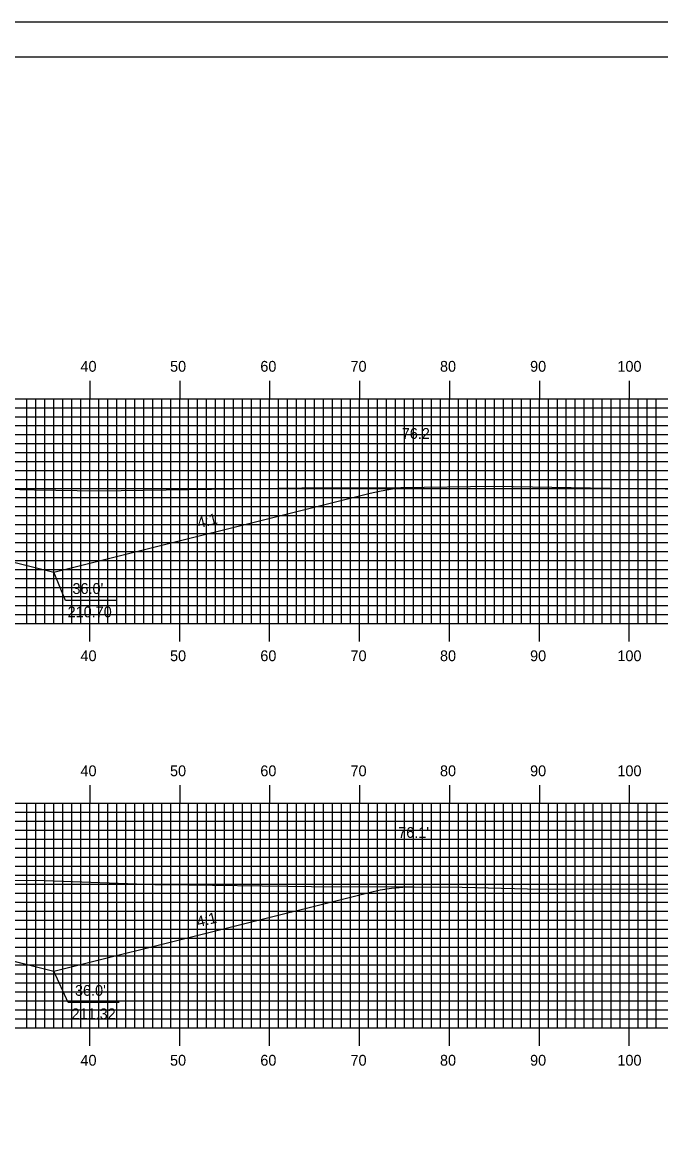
# Model space of a CAD drawing. Extents: x 1820818 to 1821161, y 442591 to 442811.
# Drawn here: x 1821016.2 to 1821087.2, y 442686.7 to 442810.5 of the extents above; entities that cross this region are included whole.
import ezdxf

# ---------------------------------------------------------------- set-up
doc = ezdxf.new("R2010")
doc.units = 0
for name, color, linetype in [('ANNOTATION', 7, 'Continuous'), ('BORDER', 7, 'Continuous'), ('D_Roadway_Centerline', 7, 'Continuous'), ('D_Roadway_SlopeLines', 7, 'Continuous'), ('D_Text_Standard', 7, 'Continuous'), ('H_V ANNOTATION', 7, 'Continuous'), ('MAJOR', 7, 'Continuous'), ('MINOR', 7, 'Continuous'), ('PLOT BOUNDARY', 7, 'Continuous'), ('S_Roadway_Centerline', 7, 'Continuous')]:
    doc.layers.add(name, color=color, linetype=linetype)

msp = doc.modelspace()

# ---------------------------------------------------------------- linework, layer by layer
at = {"layer": 'ANNOTATION'}
for points in [[(1821026.71, 442746.22), (1821021.02, 442746.22), (1821019.72, 442749.36)], [(1821027, 442701.51), (1821021.31, 442701.51), (1821019.72, 442704.99)]]:
    msp.add_lwpolyline(points, dxfattribs=at)
at = {"layer": 'BORDER'}
msp.add_lwpolyline([(1820834.12, 442596.67), (1821154.12, 442596.67), (1821154.12, 442806.67), (1820834.12, 442806.67)], close=True, dxfattribs=at)
at = {"layer": 'D_Roadway_Centerline'}
for points in [[(1820912.99, 442757.89), (1820914.24, 442757.86), (1820915.49, 442757.75), (1820916.74, 442757.56), (1820917.99, 442757.29), (1820949.54, 442749.4), (1820953.54, 442750.4), (1820963.72, 442752.94), (1820971.72, 442753.26), (1820983.72, 442753.5), (1820995.72, 442753.26), (1821005.72, 442752.86), (1821015.72, 442750.36), (1821019.72, 442749.36), (1821054.89, 442758.15), (1821056.14, 442758.43), (1821057.39, 442758.63), (1821058.64, 442758.75), (1821059.89, 442758.8)], [(1820905.5, 442715.37), (1820906.75, 442715.35), (1820908, 442715.24), (1820909.25, 442715.05), (1820910.5, 442714.78), (1820949.54, 442705.02), (1820953.54, 442706.02), (1820963.72, 442708.57), (1820971.72, 442708.89), (1820983.72, 442709.13), (1820995.72, 442708.89), (1821005.72, 442708.49), (1821015.72, 442705.99), (1821019.72, 442704.99), (1821054.78, 442713.75), (1821056.03, 442714.02), (1821057.28, 442714.22), (1821058.53, 442714.33), (1821059.78, 442714.37)]]:
    msp.add_lwpolyline(points, dxfattribs=at)
at = {"layer": 'D_Roadway_SlopeLines'}
for points in [[(1821019.72, 442749.36), (1821054.89, 442758.15), (1821056.14, 442758.43), (1821057.39, 442758.63), (1821058.64, 442758.75), (1821059.89, 442758.8)], [(1821005.72, 442752.86), (1821019.72, 442749.36)], [(1821019.72, 442704.99), (1821054.78, 442713.75), (1821056.03, 442714.02), (1821057.28, 442714.22), (1821058.53, 442714.33), (1821059.78, 442714.37)], [(1821005.72, 442708.49), (1821019.72, 442704.99)]]:
    msp.add_lwpolyline(points, dxfattribs=at)
at = {"layer": 'MAJOR'}
for p, q in [((1821023.72, 442770.67), (1821023.72, 442768.67)), ((1821033.72, 442770.67), (1821033.72, 442768.67)), ((1821043.72, 442770.67), (1821043.72, 442768.67)), ((1821053.72, 442770.67), (1821053.72, 442768.67)), ((1821063.72, 442770.67), (1821063.72, 442768.67)), ((1821073.72, 442770.67), (1821073.72, 442768.67)), ((1821083.72, 442770.67), (1821083.72, 442768.67)), ((1820843.72, 442768.67), (1821123.72, 442768.67)), ((1820843.72, 442768.67), (1821123.72, 442768.67)), ((1821023.72, 442743.67), (1821023.72, 442768.67)), ((1821033.72, 442743.67), (1821033.72, 442768.67)), ((1821043.72, 442743.67), (1821043.72, 442768.67)), ((1821053.72, 442743.67), (1821053.72, 442768.67)), ((1821063.72, 442743.67), (1821063.72, 442768.67)), ((1821073.72, 442743.67), (1821073.72, 442768.67)), ((1821083.72, 442743.67), (1821083.72, 442768.67)), ((1820843.72, 442763.67), (1821123.72, 442763.67)), ((1820843.72, 442758.67), (1821123.72, 442758.67)), ((1820843.72, 442753.67), (1821123.72, 442753.67)), ((1820843.72, 442748.67), (1821123.72, 442748.67)), ((1820843.72, 442743.67), (1821123.72, 442743.67)), ((1820843.72, 442743.67), (1821123.72, 442743.67)), ((1821023.72, 442741.66), (1821023.72, 442743.67)), ((1821033.72, 442741.66), (1821033.72, 442743.67)), ((1821043.72, 442741.66), (1821043.72, 442743.67)), ((1821053.72, 442741.66), (1821053.72, 442743.67)), ((1821063.72, 442741.66), (1821063.72, 442743.67)), ((1821073.72, 442741.66), (1821073.72, 442743.67)), ((1821083.72, 442741.66), (1821083.72, 442743.67)), ((1821023.72, 442725.67), (1821023.72, 442723.67)), ((1821033.72, 442725.67), (1821033.72, 442723.67)), ((1821043.72, 442725.67), (1821043.72, 442723.67)), ((1821053.72, 442725.67), (1821053.72, 442723.67)), ((1821063.72, 442725.67), (1821063.72, 442723.67)), ((1821073.72, 442725.67), (1821073.72, 442723.67)), ((1821083.72, 442725.67), (1821083.72, 442723.67)), ((1820843.72, 442723.67), (1821123.72, 442723.67)), ((1820843.72, 442723.67), (1821123.72, 442723.67)), ((1821023.72, 442698.67), (1821023.72, 442723.67)), ((1821033.72, 442698.67), (1821033.72, 442723.67)), ((1821043.72, 442698.67), (1821043.72, 442723.67)), ((1821053.72, 442698.67), (1821053.72, 442723.67)), ((1821063.72, 442698.67), (1821063.72, 442723.67)), ((1821073.72, 442698.67), (1821073.72, 442723.67)), ((1821083.72, 442698.67), (1821083.72, 442723.67)), ((1820843.72, 442718.67), (1821123.72, 442718.67)), ((1820843.72, 442713.67), (1821123.72, 442713.67)), ((1820843.72, 442708.67), (1821123.72, 442708.67)), ((1820843.72, 442703.67), (1821123.72, 442703.67)), ((1820843.72, 442698.67), (1821123.72, 442698.67)), ((1820843.72, 442698.67), (1821123.72, 442698.67)), ((1821023.72, 442696.66), (1821023.72, 442698.67)), ((1821033.72, 442696.66), (1821033.72, 442698.67)), ((1821043.72, 442696.66), (1821043.72, 442698.67)), ((1821053.72, 442696.66), (1821053.72, 442698.67)), ((1821063.72, 442696.66), (1821063.72, 442698.67)), ((1821073.72, 442696.66), (1821073.72, 442698.67)), ((1821083.72, 442696.66), (1821083.72, 442698.67))]:
    msp.add_line(p, q, dxfattribs=at)
at = {"layer": 'MINOR'}
for p, q in [((1821016.72, 442743.67), (1821016.72, 442768.67)), ((1821017.72, 442743.67), (1821017.72, 442768.67)), ((1821018.72, 442743.67), (1821018.72, 442768.67)), ((1821019.72, 442743.67), (1821019.72, 442768.67)), ((1821020.72, 442743.67), (1821020.72, 442768.67)), ((1821021.72, 442743.67), (1821021.72, 442768.67)), ((1821022.72, 442743.67), (1821022.72, 442768.67)), ((1821024.72, 442743.67), (1821024.72, 442768.67)), ((1821025.72, 442743.67), (1821025.72, 442768.67)), ((1821026.72, 442743.67), (1821026.72, 442768.67)), ((1821027.72, 442743.67), (1821027.72, 442768.67)), ((1821028.72, 442743.67), (1821028.72, 442768.67)), ((1821029.72, 442743.67), (1821029.72, 442768.67)), ((1821030.72, 442743.67), (1821030.72, 442768.67)), ((1821031.72, 442743.67), (1821031.72, 442768.67)), ((1821032.72, 442743.67), (1821032.72, 442768.67)), ((1821034.72, 442743.67), (1821034.72, 442768.67)), ((1821035.72, 442743.67), (1821035.72, 442768.67)), ((1821036.72, 442743.67), (1821036.72, 442768.67)), ((1821037.72, 442743.67), (1821037.72, 442768.67)), ((1821038.72, 442743.67), (1821038.72, 442768.67)), ((1821039.72, 442743.67), (1821039.72, 442768.67)), ((1821040.72, 442743.67), (1821040.72, 442768.67)), ((1821041.72, 442743.67), (1821041.72, 442768.67)), ((1821042.72, 442743.67), (1821042.72, 442768.67)), ((1821044.72, 442743.67), (1821044.72, 442768.67)), ((1821045.72, 442743.67), (1821045.72, 442768.67)), ((1821046.72, 442743.67), (1821046.72, 442768.67)), ((1821047.72, 442743.67), (1821047.72, 442768.67)), ((1821048.72, 442743.67), (1821048.72, 442768.67)), ((1821049.72, 442743.67), (1821049.72, 442768.67)), ((1821050.72, 442743.67), (1821050.72, 442768.67)), ((1821051.72, 442743.67), (1821051.72, 442768.67)), ((1821052.72, 442743.67), (1821052.72, 442768.67)), ((1821054.72, 442743.67), (1821054.72, 442768.67)), ((1821055.72, 442743.67), (1821055.72, 442768.67)), ((1821056.72, 442743.67), (1821056.72, 442768.67)), ((1821057.72, 442743.67), (1821057.72, 442768.67)), ((1821058.72, 442743.67), (1821058.72, 442768.67)), ((1821059.72, 442743.67), (1821059.72, 442768.67)), ((1821060.72, 442743.67), (1821060.72, 442768.67)), ((1821061.72, 442743.67), (1821061.72, 442768.67)), ((1821062.72, 442743.67), (1821062.72, 442768.67)), ((1821064.72, 442743.67), (1821064.72, 442768.67)), ((1821065.72, 442743.67), (1821065.72, 442768.67)), ((1821066.72, 442743.67), (1821066.72, 442768.67)), ((1821067.72, 442743.67), (1821067.72, 442768.67)), ((1821068.72, 442743.67), (1821068.72, 442768.67)), ((1821069.72, 442743.67), (1821069.72, 442768.67)), ((1821070.72, 442743.67), (1821070.72, 442768.67)), ((1821071.72, 442743.67), (1821071.72, 442768.67)), ((1821072.72, 442743.67), (1821072.72, 442768.67)), ((1821074.72, 442743.67), (1821074.72, 442768.67)), ((1821075.72, 442743.67), (1821075.72, 442768.67)), ((1821076.72, 442743.67), (1821076.72, 442768.67)), ((1821077.72, 442743.67), (1821077.72, 442768.67)), ((1821078.72, 442743.67), (1821078.72, 442768.67)), ((1821079.72, 442743.67), (1821079.72, 442768.67)), ((1821080.72, 442743.67), (1821080.72, 442768.67)), ((1821081.72, 442743.67), (1821081.72, 442768.67)), ((1821082.72, 442743.67), (1821082.72, 442768.67)), ((1821084.72, 442743.67), (1821084.72, 442768.67)), ((1821085.72, 442743.67), (1821085.72, 442768.67)), ((1821086.72, 442743.67), (1821086.72, 442768.67)), ((1820843.72, 442767.67), (1821123.72, 442767.67)), ((1820843.72, 442766.67), (1821123.72, 442766.67)), ((1820843.72, 442765.67), (1821123.72, 442765.67)), ((1820843.72, 442764.67), (1821123.72, 442764.67)), ((1820843.72, 442762.67), (1821123.72, 442762.67)), ((1820843.72, 442761.67), (1821123.72, 442761.67)), ((1820843.72, 442760.67), (1821123.72, 442760.67)), ((1820843.72, 442759.67), (1821123.72, 442759.67)), ((1820843.72, 442757.67), (1821123.72, 442757.67)), ((1820843.72, 442756.67), (1821123.72, 442756.67)), ((1820843.72, 442755.67), (1821123.72, 442755.67)), ((1820843.72, 442754.67), (1821123.72, 442754.67)), ((1820843.72, 442752.67), (1821123.72, 442752.67)), ((1820843.72, 442751.67), (1821123.72, 442751.67)), ((1820843.72, 442750.67), (1821123.72, 442750.67)), ((1820843.72, 442749.67), (1821123.72, 442749.67)), ((1820843.72, 442747.67), (1821123.72, 442747.67)), ((1820843.72, 442746.67), (1821123.72, 442746.67)), ((1820843.72, 442745.67), (1821123.72, 442745.67)), ((1820843.72, 442744.67), (1821123.72, 442744.67)), ((1821016.72, 442698.67), (1821016.72, 442723.67)), ((1821017.72, 442698.67), (1821017.72, 442723.67)), ((1821018.72, 442698.67), (1821018.72, 442723.67)), ((1821019.72, 442698.67), (1821019.72, 442723.67)), ((1821020.72, 442698.67), (1821020.72, 442723.67)), ((1821021.72, 442698.67), (1821021.72, 442723.67)), ((1821022.72, 442698.67), (1821022.72, 442723.67)), ((1821024.72, 442698.67), (1821024.72, 442723.67)), ((1821025.72, 442698.67), (1821025.72, 442723.67)), ((1821026.72, 442698.67), (1821026.72, 442723.67)), ((1821027.72, 442698.67), (1821027.72, 442723.67)), ((1821028.72, 442698.67), (1821028.72, 442723.67)), ((1821029.72, 442698.67), (1821029.72, 442723.67)), ((1821030.72, 442698.67), (1821030.72, 442723.67)), ((1821031.72, 442698.67), (1821031.72, 442723.67)), ((1821032.72, 442698.67), (1821032.72, 442723.67)), ((1821034.72, 442698.67), (1821034.72, 442723.67)), ((1821035.72, 442698.67), (1821035.72, 442723.67)), ((1821036.72, 442698.67), (1821036.72, 442723.67)), ((1821037.72, 442698.67), (1821037.72, 442723.67)), ((1821038.72, 442698.67), (1821038.72, 442723.67)), ((1821039.72, 442698.67), (1821039.72, 442723.67)), ((1821040.72, 442698.67), (1821040.72, 442723.67)), ((1821041.72, 442698.67), (1821041.72, 442723.67)), ((1821042.72, 442698.67), (1821042.72, 442723.67)), ((1821044.72, 442698.67), (1821044.72, 442723.67)), ((1821045.72, 442698.67), (1821045.72, 442723.67)), ((1821046.72, 442698.67), (1821046.72, 442723.67)), ((1821047.72, 442698.67), (1821047.72, 442723.67)), ((1821048.72, 442698.67), (1821048.72, 442723.67)), ((1821049.72, 442698.67), (1821049.72, 442723.67)), ((1821050.72, 442698.67), (1821050.72, 442723.67)), ((1821051.72, 442698.67), (1821051.72, 442723.67)), ((1821052.72, 442698.67), (1821052.72, 442723.67)), ((1821054.72, 442698.67), (1821054.72, 442723.67)), ((1821055.72, 442698.67), (1821055.72, 442723.67)), ((1821056.72, 442698.67), (1821056.72, 442723.67)), ((1821057.72, 442698.67), (1821057.72, 442723.67)), ((1821058.72, 442698.67), (1821058.72, 442723.67)), ((1821059.72, 442698.67), (1821059.72, 442723.67)), ((1821060.72, 442698.67), (1821060.72, 442723.67)), ((1821061.72, 442698.67), (1821061.72, 442723.67)), ((1821062.72, 442698.67), (1821062.72, 442723.67)), ((1821064.72, 442698.67), (1821064.72, 442723.67)), ((1821065.72, 442698.67), (1821065.72, 442723.67)), ((1821066.72, 442698.67), (1821066.72, 442723.67)), ((1821067.72, 442698.67), (1821067.72, 442723.67)), ((1821068.72, 442698.67), (1821068.72, 442723.67)), ((1821069.72, 442698.67), (1821069.72, 442723.67)), ((1821070.72, 442698.67), (1821070.72, 442723.67)), ((1821071.72, 442698.67), (1821071.72, 442723.67)), ((1821072.72, 442698.67), (1821072.72, 442723.67)), ((1821074.72, 442698.67), (1821074.72, 442723.67)), ((1821075.72, 442698.67), (1821075.72, 442723.67)), ((1821076.72, 442698.67), (1821076.72, 442723.67)), ((1821077.72, 442698.67), (1821077.72, 442723.67)), ((1821078.72, 442698.67), (1821078.72, 442723.67)), ((1821079.72, 442698.67), (1821079.72, 442723.67)), ((1821080.72, 442698.67), (1821080.72, 442723.67)), ((1821081.72, 442698.67), (1821081.72, 442723.67)), ((1821082.72, 442698.67), (1821082.72, 442723.67)), ((1821084.72, 442698.67), (1821084.72, 442723.67)), ((1821085.72, 442698.67), (1821085.72, 442723.67)), ((1821086.72, 442698.67), (1821086.72, 442723.67)), ((1820843.72, 442722.67), (1821123.72, 442722.67)), ((1820843.72, 442721.67), (1821123.72, 442721.67)), ((1820843.72, 442720.67), (1821123.72, 442720.67)), ((1820843.72, 442719.67), (1821123.72, 442719.67)), ((1820843.72, 442717.67), (1821123.72, 442717.67)), ((1820843.72, 442716.67), (1821123.72, 442716.67)), ((1820843.72, 442715.67), (1821123.72, 442715.67)), ((1820843.72, 442714.67), (1821123.72, 442714.67)), ((1820843.72, 442712.67), (1821123.72, 442712.67)), ((1820843.72, 442711.67), (1821123.72, 442711.67)), ((1820843.72, 442710.67), (1821123.72, 442710.67)), ((1820843.72, 442709.67), (1821123.72, 442709.67)), ((1820843.72, 442707.67), (1821123.72, 442707.67)), ((1820843.72, 442706.67), (1821123.72, 442706.67)), ((1820843.72, 442705.67), (1821123.72, 442705.67)), ((1820843.72, 442704.67), (1821123.72, 442704.67)), ((1820843.72, 442702.67), (1821123.72, 442702.67)), ((1820843.72, 442701.67), (1821123.72, 442701.67)), ((1820843.72, 442700.67), (1821123.72, 442700.67)), ((1820843.72, 442699.67), (1821123.72, 442699.67))]:
    msp.add_line(p, q, dxfattribs=at)
at = {"layer": 'PLOT BOUNDARY'}
msp.add_lwpolyline([(1820817.93, 442590.55), (1821157.93, 442590.55), (1821157.93, 442810.55), (1820817.93, 442810.55)], close=True, dxfattribs=at)
at = {"layer": 'S_Roadway_Centerline'}
for points in [[(1821007.84, 442758.74), (1821017.58, 442758.53), (1821024.68, 442758.43), (1821047.3, 442758.76), (1821058.33, 442758.78), (1821068.64, 442758.93), (1821081.55, 442758.71), (1821085.17, 442758.69), (1821097.88, 442758.51), (1821102.42, 442758.49), (1821114.65, 442758.38), (1821118.76, 442758.39), (1821123.72, 442758.33)], [(1821013.58, 442715.11), (1821018.78, 442715.08), (1821030.94, 442714.64), (1821031.88, 442714.61), (1821048.38, 442714.41), (1821059.62, 442714.37), (1821065.14, 442714.31), (1821072.42, 442714.15), (1821081.96, 442714.11), (1821085.87, 442714.14), (1821098.06, 442714.09), (1821098.23, 442714.09), (1821098.71, 442714.1), (1821100.8, 442714.05), (1821116.3, 442713.91), (1821121.24, 442713.93), (1821123.72, 442713.96)]]:
    msp.add_lwpolyline(points, dxfattribs=at)

# ---------------------------------------------------------------- texts
at = {"layer": 'ANNOTATION'}
for p in [(1821035.84, 442754.25), (1821035.78, 442709.86)]:
    msp.add_text('4:1', height=1.2, rotation=14.0362, dxfattribs=at).set_placement(p)
for s, p in [("36.0'", (1821021.8, 442746.95)), ('210.70', (1821021.26, 442744.35)), ("36.0'", (1821022.08, 442702.24)), ('211.32', (1821021.7, 442699.64))]:
    msp.add_text(s, height=1.2, dxfattribs=at).set_placement(p)
at = {"layer": 'D_Text_Standard'}
for s, p in [("76.2'", (1821058.42, 442764.2)), ("76.1'", (1821058.02, 442719.81))]:
    msp.add_text(s, height=1.2, dxfattribs=at).set_placement(p)
at = {"layer": 'H_V ANNOTATION'}
for s, p in [('40', (1821022.69, 442771.67)), ('50', (1821032.65, 442771.67)), ('60', (1821042.69, 442771.67)), ('70', (1821052.72, 442771.67)), ('80', (1821062.67, 442771.67)), ('90', (1821072.69, 442771.67)), ('100', (1821082.4, 442771.67)), ('40', (1821022.69, 442739.47)), ('50', (1821032.65, 442739.47)), ('60', (1821042.69, 442739.47)), ('70', (1821052.72, 442739.47)), ('80', (1821062.67, 442739.47)), ('90', (1821072.69, 442739.47)), ('100', (1821082.4, 442739.47)), ('40', (1821022.69, 442726.67)), ('50', (1821032.65, 442726.67)), ('60', (1821042.69, 442726.67)), ('70', (1821052.72, 442726.67)), ('80', (1821062.67, 442726.67)), ('90', (1821072.69, 442726.67)), ('100', (1821082.4, 442726.67)), ('40', (1821022.69, 442694.47)), ('50', (1821032.65, 442694.47)), ('60', (1821042.69, 442694.47)), ('70', (1821052.72, 442694.47)), ('80', (1821062.67, 442694.47)), ('90', (1821072.69, 442694.47)), ('100', (1821082.4, 442694.47))]:
    msp.add_text(s, height=1.2, dxfattribs=at).set_placement(p)

doc.saveas('drawing.dxf')
